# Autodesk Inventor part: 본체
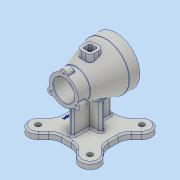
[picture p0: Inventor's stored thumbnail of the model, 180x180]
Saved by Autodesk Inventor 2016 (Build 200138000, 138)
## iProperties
Created: 2018-03
Part Number: 본체
Material: 알루미늄 6061
Document SubType Name: Modeling
Designer: 605-15
Density: 2.7 g/cm^3
Appearance: 알루미늄 - 평지
Mass: 1046.88 g
Surface Area: 900.56 cm^2
Volume: 387.732 cm^3
Author: 605-15
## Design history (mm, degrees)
sketch "스케치1"
  geometry: L1 (0, 0)-(-45, 0); L2 (-45, 0)-(-45, 20); L3 (0, 0)-(0, 100); L4 (0, 100)-(-27.5, 100); L5 (-27.5, 100)-(-27.5, 77); L6 (-27.5, 77)-(-45, 20); L7 (0, 0)-(0, -41.292)
  constraints: 14 end point, 3 perpendicular, 2 vertical, 1 horizontal
  dimensions: "d0" = 45 distance of L1.start L1.end; "d1" = 20 distance of L1.end L2.end; "d3" = 100 distance of L1.start L3.end; "d4" = 27.5 distance of L3.end L4.end; "d5" = 23 distance of L4.end L5.end
revolve "회전1" sketch "스케치1" stored, may be unused: angle "d6" = 90 deg
sketch "스케치2" dims "d7" = 55
  geometry: L1 (0, 0)-(0, 66.107); C1 r 7 at (0, 27.5); 1 further point
  constraints: 2 end point, 1 centre point, 1 coincident, 1 point on line, 1 vertical, 1 vertical alignment, 2 other
  dimensions: "d8" = 7 radius of C1
extrude "돌출1" join sketch "스케치2" distance "d9" = 15; taper "d10" = 0 deg
sketch "스케치3"
  geometry: A1 r 27.5 centre (0, -27.5) between (26.516, -34.792) and (6.943, -0.891) reference; A2 r 7 centre (0, 0) between (6.943, -0.891) and (-6.943, -0.891) reference; A3 r 27.5 centre (0, -27.5) between (-6.943, -0.891) and (-26.516, -34.792) reference; A4 r 7 centre (-23.816, -41.25) between (-26.516, -34.792) and (-19.573, -46.817) reference; A5 r 27.5 centre (0, -27.5) between (-19.573, -46.817) and (19.573, -46.817) reference; A6 r 7 centre (23.816, -41.25) between (19.573, -46.817) and (26.516, -34.792) reference; 4 further points
  constraints: 3 coincident
hole "구멍1" sketch "스케치3" at (0, 0), (23.816, -41.25), (-23.816, -41.25) diameter "d14" = 3.242; stored, may be unused: countersink angle "d18" = 90 deg, drill point angle "d20" = 118 deg; dims "d15" = 9, "d16" = 4, "d17" = 2, "d19" = 11
sketch "스케치4"
  geometry: C1 r 35 at (0, 0); 1 further point
  constraints: 1 centre point, 1 coincident
  dimensions: "d21" = 70 diameter of C1
extrude "돌출2" cut sketch "스케치4" distance "d22" = 23; taper "d23" = 0 deg
sketch "스케치5"
  geometry: C1 r 26 at (0, 0); 1 further point
  constraints: 1 centre point, 1 coincident
  dimensions: "d24" = 52 diameter of C1
extrude "돌출3" cut sketch "스케치5" distance "d25" = 47; taper "d26" = 0 deg
sketch "스케치6"
  geometry: C1 r 20 at (0, 0); 1 further point
  constraints: 1 centre point, 1 coincident
  dimensions: "d27" = 40 diameter of C1
extrude "돌출4" cut sketch "스케치6" stored distance "d28" = 47; taper "d29" = 0 deg
sketch "스케치7" dims "d30" = 80
  geometry: L1 (0, 0)-(0, -68.967); 2 further points
  constraints: 2 end point, 1 coincident, 1 point on line, 1 vertical, 1 vertical alignment, 2 other
hole "구멍2" sketch "스케치7" at (0, -40) diameter "d31" = 3.242; stored, may be unused: countersink angle "d35" = 90 deg, drill point angle "d37" = 118 deg; dims "d32" = 9, "d33" = 4, "d34" = 2, "d36" = 11
node "작업 평면1"
sketch "스케치8"
  geometry: L1 (45, 20)-(-45, 20) reference; L2 (45, 0)-(-45, 0) reference; L3 (12.5, 37.5)-(-12.5, 37.5); L4 (-12.5, 37.5)-(-12.5, 62.5); L5 (-12.5, 62.5)-(12.5, 62.5); L6 (12.5, 62.5)-(12.5, 37.5); L7 (12.5, 50)-(65.887, 50); L8 (7.5, 42.5)-(-7.5, 42.5); L9 (-7.5, 42.5)-(-7.5, 57.5); L10 (-7.5, 57.5)-(7.5, 57.5); L11 (7.5, 57.5)-(7.5, 42.5); 6 further points
  constraints: 18 end point, 6 midpoint, 4 parallel, 3 horizontal, 2 perpendicular, 2 vertical alignment, 1 horizontal alignment
  dimensions: "d42" = 25 distance of L5.end L3.start; "d43" = 25 distance of L4.end L5.end; "d44" = 50 distance between parallel lines of L7 L2; "d45" = 15 distance of L10.end L8.start; "d46" = 15 distance of L8.start L8.end
  node "투영된 루프2"
extrude "돌출5" join sketch "스케치8" stored distance "d47" = 47; taper "d48" = 0 deg
extrude "돌출6" cut sketch "스케치8" stored distance "d49" = 47; taper "d50" = 0 deg
node "작업 평면2"
sketch "스케치9"
  geometry: L1 (45, 20)-(-45, 20) reference; L2 (45, 0)-(-45, 0) reference; L3 (0, 50)-(-72.752, -22.752); L4 (0, 50)-(0, -81.55); L5 (45, 5)-(-45, 95); L6 (-45, 5)-(45, 95); L7 (9.189, 5)-(-9.189, 5); L8 (-45, 40.811)-(-45, 59.189); L9 (-9.189, 95)-(9.189, 95); L10 (45, 5)-(-45, 95); L11 (-45, 5)-(45, 95); L12 (-62.225, 13.23)-(-52.322, 23.134); L13 (-36.77, -12.225)-(-24.544, 0); L14 (36.77, -12.225)-(26.866, -2.322); L15 (62.225, 13.23)-(50, 25.456); L16 (62.225, 86.77)-(52.322, 76.866); L17 (36.77, 112.225)-(24.544, 100); L18 (-36.77, 112.225)-(-26.866, 102.322); L19 (-62.225, 86.77)-(-50, 74.544); L20 (45, 59.189)-(45, 40.811); C1 r 70 at (0, 50); A1 r 25 centre (-9.189, -20) between (-9.189, 5) and (-26.866, -2.322); A2 r 25 centre (-70, 40.811) between (-52.322, 23.134) and (-45, 40.811); A3 r 18 centre (-49.497, 0.503) between (-60.483, 14.761) and (-35.239, -10.483); A4 r 18 centre (49.497, 0.503) between (35.239, -10.483) and (60.483, 14.761); A5 r 25 centre (9.189, -20) between (26.866, -2.322) and (9.189, 5); A6 r 25 centre (70, 40.811) between (45, 40.811) and (52.322, 23.134); A7 r 18 centre (49.497, 99.497) between (60.483, 85.239) and (35.239, 110.483); A8 r 25 centre (70, 59.189) between (52.322, 76.866) and (45, 59.189); A9 r 25 centre (9.189, 120) between (9.189, 95) and (26.866, 102.322); A10 r 18 centre (-49.497, 99.497) between (-35.239, 110.483) and (-60.483, 85.239); A11 r 25 centre (-9.189, 120) between (-26.866, 102.322) and (-9.189, 95); A12 r 25 centre (-70, 59.189) between (-45, 59.189) and (-52.322, 76.866); 2 further points
  constraints: 37 end point, 32 point on circle, 13 centre point, 8 tangent, 6 point on line, 5 midpoint, 2 parallel, 2 perpendicular, 2 vertical alignment, 1 coincident, 1 equal radius, 1 horizontal, 1 vertical, 69 other
  dimensions: "d53" = 50 distance from line of L2 L3.start; "d54" = 45 deg angle of L4 L3; "d63" = 90 distance of L11.start L10.end; "d64" = 90 distance of L10.start L11.start; "d68" = 140 diameter of C1; "d71" = 360 deg dimension on C1.centre A3.centre (derived); "d73" = 25 radius of A8; "d74" = 18 radius of A7; "d75" = 45 deg angle of L1 L11; "d76" = 45 deg angle of L1 L6; "d77" = 45 deg angle of L1 L10; "d78" = 75 distance between parallel lines of L1 L9; "d79" = 66.76955 distance from line of L16.start L1; "d80" = 65.23874 distance from line of A7.start L1; "d81" = 5.23874 distance from line of A4.end L1; "d82" = 75 distance from line of L11.end L1; "d83" = 75 distance from line of L6.end L1; "d84" = 15 distance from line of L10.start L1; "d85" = 15 distance from line of L5.start L1; "d86" = 101.54986 distance from line of L4.end L1; "d87" = 75 distance from line of L5.end L1; "d88" = 15 distance from line of L6.start L1; "d89" = 42.75198 distance from line of L3.end L1
extrude "돌출7" join sketch "스케치9" distance "d90" = 12; taper "d91" = 0 deg
sketch "스케치10"
  geometry: L1 (36.77, -12.225)-(26.866, -2.322) reference; L2 (9.189, 5)-(-9.189, 5) reference; L3 (-26.866, -2.322)-(-36.77, -12.225) reference; L4 (-62.225, 13.23)-(-52.322, 23.134) reference; L5 (-45, 40.811)-(-45, 59.189) reference; L6 (-52.322, 76.866)-(-62.225, 86.77) reference; L7 (-36.77, 112.225)-(-26.866, 102.322) reference; L8 (-9.189, 95)-(9.189, 95) reference; L9 (26.866, 102.322)-(36.77, 112.225) reference; L10 (62.225, 86.77)-(52.322, 76.866) reference; L11 (45, 59.189)-(45, 40.811) reference; L12 (52.322, 23.134)-(62.225, 13.23) reference; L13 (-45, 50)-(45, 50); L14 (-4, 13)-(4, 13); L15 (4, 87)-(-4, 87); L16 (-4, 13)-(4, 87); L17 (4, 13)-(-4, 87); L18 (-24, 54)-(-24, 46); L19 (24, 46)-(24, 54); L20 (-24, 54)-(24, 46); L21 (-24, 46)-(-4, 46); L22 (24, 54)-(0, 50); L23 (-4, 49.333)-(-24, 46); L24 (-4, 87)-(-4, 54); L25 (24, 54)-(4, 54); L26 (-4, 54)-(-24, 54); L27 (4, 46)-(24, 46); L28 (4, 13)-(4, 46); L29 (4, 54)-(4, 87); L30 (-4, 46)-(-4, 13); A1 r 25 centre (9.189, -20) between (26.866, -2.322) and (9.189, 5) reference; A2 r 25 centre (-9.189, -20) between (-9.189, 5) and (-26.866, -2.322) reference; A3 r 18 centre (-49.497, 0.503) between (-62.225, 13.23) and (-36.77, -12.225) reference; A4 r 25 centre (-70, 40.811) between (-52.322, 23.134) and (-45, 40.811) reference; A5 r 25 centre (-70, 59.189) between (-45, 59.189) and (-52.322, 76.866) reference; A6 r 18 centre (-49.497, 99.497) between (-36.77, 112.225) and (-62.225, 86.77) reference; A7 r 25 centre (-9.189, 120) between (-26.866, 102.322) and (-9.189, 95) reference; A8 r 25 centre (9.189, 120) between (9.189, 95) and (26.866, 102.322) reference; A9 r 18 centre (49.497, 99.497) between (62.225, 86.77) and (36.77, 112.225) reference; A10 r 25 centre (70, 59.189) between (52.322, 76.866) and (45, 59.189) reference; A11 r 25 centre (70, 40.811) between (45, 40.811) and (52.322, 23.134) reference; A12 r 18 centre (49.497, 0.503) between (36.77, -12.225) and (62.225, 13.23) reference; 1 further point
  constraints: 36 end point, 10 parallel, 6 midpoint, 4 perpendicular, 3 horizontal
  dimensions: "d92" = 8 distance of L15.start L15.end; "d93" = 74 distance of L15.end L14.start; "d94" = 8 distance of L18.start L18.end; "d95" = 48 distance of L19.end L18.start; "d96" = 144.462 deg angle of L10 L22; "d97" = 125.538 deg angle of L10 L20; "d98" = 51.1702 deg angle of L10 L17; "d99" = 38.8298 deg angle of L10 L16; "d100" = 144.462 deg angle of L10 L23; "d101" = 49 distance between parallel lines of L2 L25; "d102" = 20.35702 distance from line of L23.start L10
extrude "돌출8" join sketch "스케치10" stored distance "d103" = 12; taper "d104" = 0 deg
sketch "스케치11"
  geometry: L1 (36.77, -12.225)-(26.866, -2.322) reference; L2 (9.189, 5)-(-9.189, 5) reference; L3 (-26.866, -2.322)-(-36.77, -12.225) reference; L4 (-62.225, 13.23)-(-52.322, 23.134) reference; L5 (-45, 40.811)-(-45, 59.189) reference; L6 (-52.322, 76.866)-(-62.225, 86.77) reference; L7 (-36.77, 112.225)-(-26.866, 102.322) reference; L8 (-9.189, 95)-(9.189, 95) reference; L9 (26.866, 102.322)-(36.77, 112.225) reference; L10 (62.225, 86.77)-(52.322, 76.866) reference; L11 (45, 59.189)-(45, 40.811) reference; L12 (52.322, 23.134)-(62.225, 13.23) reference; L13 (9.189, 5)-(-9.189, 5) reference; L14 (-9.189, 95)-(9.189, 95) reference; A1 r 25 centre (9.189, -20) between (26.866, -2.322) and (9.189, 5) reference; A2 r 25 centre (-9.189, -20) between (-9.189, 5) and (-26.866, -2.322) reference; A3 r 18 centre (-49.497, 0.503) between (-62.225, 13.23) and (-36.77, -12.225) reference; A4 r 25 centre (-70, 40.811) between (-52.322, 23.134) and (-45, 40.811) reference; A5 r 25 centre (-70, 59.189) between (-45, 59.189) and (-52.322, 76.866) reference; A6 r 18 centre (-49.497, 99.497) between (-36.77, 112.225) and (-62.225, 86.77) reference; A7 r 25 centre (-9.189, 120) between (-26.866, 102.322) and (-9.189, 95) reference; A8 r 25 centre (9.189, 120) between (9.189, 95) and (26.866, 102.322) reference; A9 r 18 centre (49.497, 99.497) between (62.225, 86.77) and (36.77, 112.225) reference; A10 r 25 centre (70, 59.189) between (52.322, 76.866) and (45, 59.189) reference; A11 r 25 centre (70, 40.811) between (45, 40.811) and (52.322, 23.134) reference; A12 r 18 centre (49.497, 0.503) between (36.77, -12.225) and (62.225, 13.23) reference; 5 further points
  constraints: 4 coincident
hole "구멍3" sketch "스케치11" at (49.497, 0.503), (-49.497, 0.503), (-49.497, 99.497), (49.497, 99.497) diameter "d106" = 10; stored, may be unused: countersink angle "d110" = 90 deg, drill point angle "d112" = 118 deg; dims "d107" = 9, "d108" = 4, "d109" = 2, "d111" = 10
sketch "스케치12"
  geometry: L1 (33, 48.85)-(33, 51.15); L2 (33, 51.15)-(37, 51.15); L3 (37, 51.15)-(37, 48.85); L4 (37, 48.85)-(33, 48.85); L5 (36.77, -12.225)-(26.866, -2.322) reference; L6 (9.189, 5)-(-9.189, 5) reference; L7 (-26.866, -2.322)-(-36.77, -12.225) reference; L8 (-62.225, 13.23)-(-52.322, 23.134) reference; L9 (-45, 40.811)-(-45, 59.189) reference; L10 (-52.322, 76.866)-(-62.225, 86.77) reference; L11 (-36.77, 112.225)-(-26.866, 102.322) reference; L12 (-9.189, 95)-(9.189, 95) reference; L13 (26.866, 102.322)-(36.77, 112.225) reference; L14 (62.225, 86.77)-(52.322, 76.866) reference; L15 (45, 59.189)-(45, 40.811) reference; L16 (52.322, 23.134)-(62.225, 13.23) reference; C1 r 5 at (-49.497, 99.497) reference; C2 r 5 at (49.497, 0.503) reference; C3 r 5 at (-49.497, 0.503) reference; C4 r 5 at (49.497, 99.497) reference; A1 r 25 centre (9.189, -20) between (26.866, -2.322) and (9.189, 5) reference; A2 r 25 centre (-9.189, -20) between (-9.189, 5) and (-26.866, -2.322) reference; A3 r 18 centre (-49.497, 0.503) between (-62.225, 13.23) and (-36.77, -12.225) reference; A4 r 25 centre (-70, 40.811) between (-52.322, 23.134) and (-45, 40.811) reference; A5 r 25 centre (-70, 59.189) between (-45, 59.189) and (-52.322, 76.866) reference; A6 r 18 centre (-49.497, 99.497) between (-36.77, 112.225) and (-62.225, 86.77) reference; A7 r 25 centre (-9.189, 120) between (-26.866, 102.322) and (-9.189, 95) reference; A8 r 25 centre (9.189, 120) between (9.189, 95) and (26.866, 102.322) reference; A9 r 18 centre (49.497, 99.497) between (62.225, 86.77) and (36.77, 112.225) reference; A10 r 25 centre (70, 59.189) between (52.322, 76.866) and (45, 59.189) reference; A11 r 25 centre (70, 40.811) between (45, 40.811) and (52.322, 23.134) reference; A12 r 18 centre (49.497, 0.503) between (36.77, -12.225) and (62.225, 13.23) reference; 3 further points
  constraints: 2 midpoint, 1 horizontal alignment, 2 other
  dimensions: "d113" = 4 distance of L1.end L2.end; "d114" = 33 horizontal distance of L1.start point (0, 0)
feature "엠보싱1" sketch "스케치12" dims "d115" = 0.5, "d116" = 0
fillet "모깎기1" dims "d117" = 3
fillet "모깎기2" dims "d118" = 1
fillet "모깎기3" dims "d122" = 8
fillet "모깎기4" dims "d123" = 3
fillet "모깎기5" dims "d124" = 3
fillet "모깎기7" dims "d126" = 3
fillet "모깎기8" dims "d127" = 3
fillet "모깎기11" dims "d130" = 3
fillet "모깎기12" dims "d131" = 3
chamfer "모따기1" distance "d132" = 1; stored, may be unused: second distance "d133" = 2, angle "d134" = 45 deg
chamfer "모따기2" distance "d135" = 3; stored, may be unused: second distance "d136" = 2, angle "d137" = 45 deg
fillet "모깎기13" dims "d138" = 1
fillet "모깎기14" dims "d139" = 3
fillet "모깎기15" dims "d140" = 3
fillet "모깎기16" dims "d141" = 3
node "솔리드1"
pattern_circular "원형 패턴1" dims angle "d12" = 360 deg
pattern_circular "원형 패턴2" dims angle "d39" = 360 deg
pattern_circular "원형 패턴3" dims angle "d120" = 360 deg
node "투영된 루프1"
node "투영된 루프3"
node "투영된 루프4"
node "투영된 루프5"
node "투영된 루프6"
other parameters: "d41" = -45, "d51" = 82, "d55" = 18, "d58" = 25, "d60" = 22.41058, "d62" = 25, "d65" = 36, "d66" = 25, "d67" = 25
